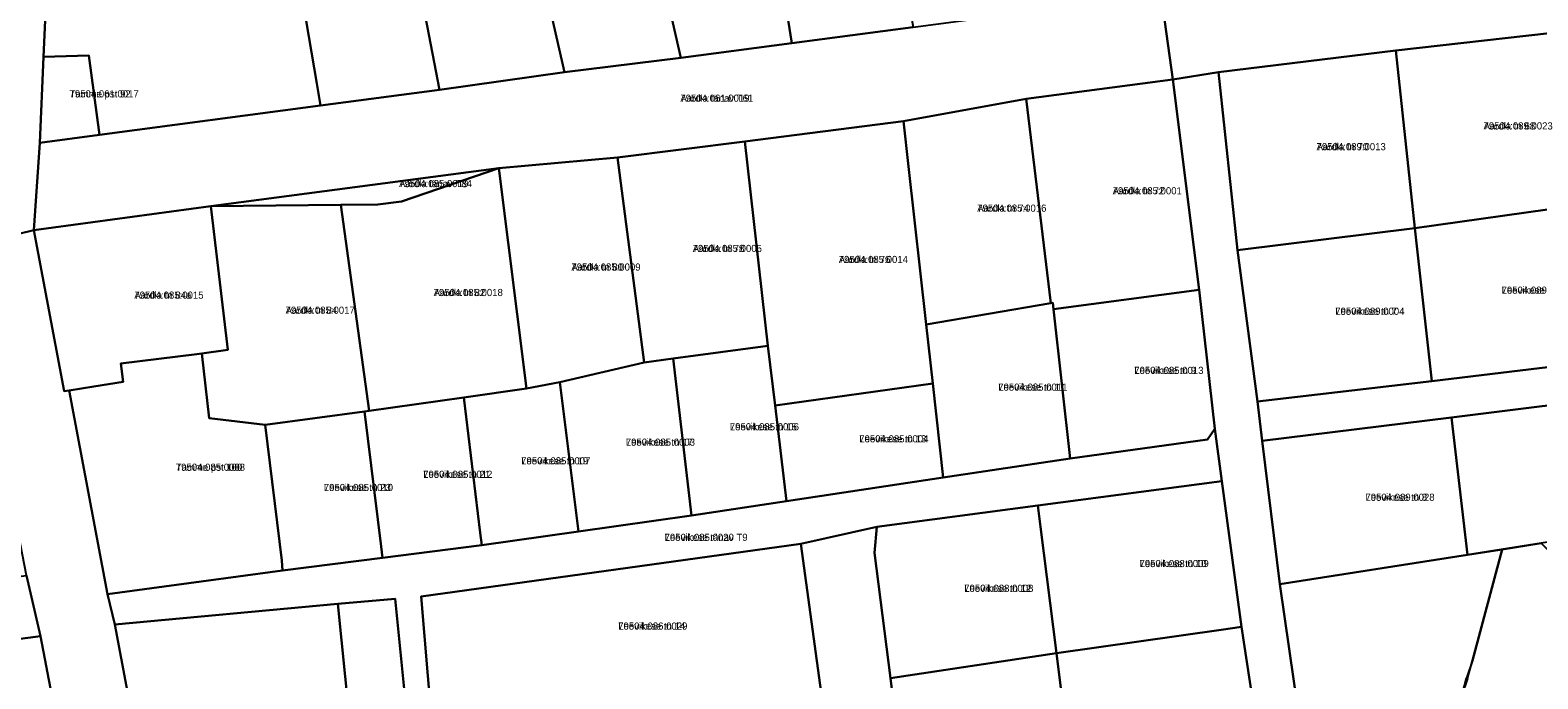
# Model space of a CAD drawing. Extents: x 643847 to 663718, y 6468443 to 6482775.
# Drawn here: x 657831.9 to 658147.9, y 6471252.2 to 6471388.2 of the extents above; entities that cross this region are included whole.
import ezdxf

# ---------------------------------------------------------------- set-up
doc = ezdxf.new("R2010")
doc.units = 0
for name, color, linetype in [('L_AADRESS', 7, 'Continuous'), ('PIIR', 7, 'Continuous'), ('TUNNUS', 7, 'Continuous')]:
    doc.layers.add(name, color=color, linetype=linetype)

msp = doc.modelspace()

# ---------------------------------------------------------------- linework, layer by layer
at = {"layer": 'PIIR'}
for points in [[(657847.52, 6471587.53), (657845.97, 6471567.52), (657842.41, 6471521.91), (657839.77, 6471486.67), (657837.5, 6471452.36), (657837.22, 6471437.59), (657835.93, 6471408.73), (657834.76, 6471382.58), (657833.95, 6471364.57), (657832.75, 6471346.26), (657818.06, 6471342.66), (657815.82, 6471355.91), (657818.38, 6471384.03), (657820.03, 6471406.57), (657821.19, 6471434.16), (657823.07, 6471447.88), (657824.85, 6471478.3), (657827.44, 6471517.38), (657828.11, 6471527.43), (657829.93, 6471552.31), (657832.8, 6471591.95)], [(658150.36, 6471387.58), (658118.18, 6471383.93), (658080.99, 6471379.35), (658071.44, 6471377.84), (658068.39, 6471400.1), (658079.89, 6471397.11), (658105.48, 6471400.5), (658104.9, 6471404.89), (658134.3, 6471408.73), (658134.78, 6471404.38), (658153.89, 6471406.9)], [(658157.59, 6471138.6), (658131.21, 6471165.2), (658120.98, 6471175.55), (658094.63, 6471202.06), (658093.37, 6471210.77), (658089.82, 6471236.97), (658085.82, 6471263.08), (658081.73, 6471293.65), (658080.28, 6471304.56), (658076.97, 6471333.75), (658071.44, 6471377.84), (658080.99, 6471379.35), (658084.98, 6471342.07), (658089.2, 6471310.31), (658090.2, 6471302.05), (658093.85, 6471272.01), (658099.83, 6471230.86), (658103.42, 6471206.17), (658120.45, 6471189), (658129.95, 6471179.44), (658131.89, 6471181.22), (658134.07, 6471179.04), (658132.12, 6471177.25), (658168.44, 6471140.66)], [(657841.55, 6471222.32), (657834.14, 6471261.11), (657831.15, 6471273.87), (657825.18, 6471304.55), (657818.06, 6471342.66), (657832.75, 6471346.26), (657839.08, 6471312.46), (657840.14, 6471312.63), (657848.14, 6471269.95), (657849.67, 6471263.57), (657853.69, 6471242.4)], [(657912.92, 6471224.23), (657908.42, 6471268.94), (657896.47, 6471267.87), (657849.67, 6471263.57), (657848.14, 6471269.95), (657884.82, 6471274.9), (657905.78, 6471277.58), (657926.6, 6471280.2), (657946.86, 6471283.07), (657970.57, 6471286.44), (657990.44, 6471289.43), (658023.3, 6471294.37), (658049.96, 6471298.38), (658078.69, 6471302.37), (658080.28, 6471304.56), (658081.73, 6471293.65), (658043.18, 6471288.51), (658009.43, 6471284.02), (657993.46, 6471280.49), (657913.9, 6471269.47), (657916.02, 6471244.49)], [(657997.92, 6471247.76), (657993.46, 6471280.49), (658009.43, 6471284.02), (658008.95, 6471278.59), (658012.26, 6471252.31), (658015.5, 6471226.51)]]:
    msp.add_lwpolyline(points, dxfattribs=at)
for points in [[(657991.61, 6471385.43), (657985.6, 6471423.21), (658002.42, 6471425.45), (658010.18, 6471426.44), (658017.04, 6471388.8)], [(657991.61, 6471385.43), (657968.36, 6471382.36), (657959.71, 6471420.04), (657980.6, 6471422.61), (657985.6, 6471423.21)], [(657943.94, 6471379.4), (657935.41, 6471416.76), (657959.71, 6471420.04), (657968.36, 6471382.36)], [(657917.76, 6471375.66), (657911.1, 6471410.21), (657935.41, 6471416.76), (657943.94, 6471379.4)], [(657846.48, 6471366.23), (657844.25, 6471382.89), (657834.76, 6471382.58), (657835.93, 6471408.73), (657840.14, 6471408.44), (657863.78, 6471413.17), (657885.43, 6471416.08), (657887.02, 6471406.64), (657892.03, 6471377.02), (657892.82, 6471372.36)], [(657892.82, 6471372.36), (657892.03, 6471377.02), (657887.02, 6471406.64), (657909.7, 6471410), (657911.1, 6471410.21), (657917.76, 6471375.66)], [(658040.27, 6471396.4), (658068.39, 6471400.1), (658071.44, 6471377.84), (658040.7, 6471373.77), (658015, 6471369.11), (657981.76, 6471364.87), (657955.06, 6471361.46), (657930.15, 6471359.24), (657869.84, 6471351.31), (657832.75, 6471346.26), (657833.95, 6471364.57), (657846.48, 6471366.23), (657892.82, 6471372.36), (657917.76, 6471375.66), (657943.94, 6471379.4), (657968.36, 6471382.36), (657991.61, 6471385.43), (658017.04, 6471388.8), (658040.78, 6471391.94)], [(658150.36, 6471387.58), (658151.63, 6471378.13), (658154.96, 6471353.35), (658154.93, 6471351.27), (658122.17, 6471346.69), (658118.18, 6471383.93)], [(657834.76, 6471382.58), (657844.25, 6471382.89), (657846.48, 6471366.23), (657833.95, 6471364.57)], [(658118.18, 6471383.93), (658122.17, 6471346.69), (658084.98, 6471342.07), (658080.99, 6471379.35)], [(658071.44, 6471377.84), (658076.97, 6471333.75), (658046.46, 6471329.72), (658046.31, 6471331.02), (658045.9, 6471330.96), (658040.7, 6471373.77)], [(658015, 6471369.11), (658040.7, 6471373.77), (658045.9, 6471330.96), (658019.74, 6471326.49), (658016.05, 6471359.62)], [(658015, 6471369.11), (658016.05, 6471359.62), (658019.74, 6471326.49), (658021.11, 6471314.07), (657988.07, 6471309.49), (657986.58, 6471321.98), (657981.76, 6471364.87)], [(657981.76, 6471364.87), (657986.58, 6471321.98), (657966.74, 6471319.33), (657960.63, 6471318.52), (657955.06, 6471361.46)], [(657955.06, 6471361.46), (657960.63, 6471318.52), (657943, 6471314.38), (657935.99, 6471313.08), (657930.15, 6471359.24)], [(657869.84, 6471351.31), (657930.15, 6471359.24), (657909.78, 6471352.28), (657904.81, 6471351.63), (657897.04, 6471351.56)], [(657897.04, 6471351.56), (657904.81, 6471351.63), (657909.78, 6471352.28), (657930.15, 6471359.24), (657935.99, 6471313.08), (657922.85, 6471311.17), (657903.02, 6471308.39)], [(657869.84, 6471351.31), (657873.39, 6471321.19), (657867.95, 6471320.36), (657866.86, 6471320.23), (657850.97, 6471318.3), (657851.42, 6471314.42), (657845.32, 6471313.44), (657840.14, 6471312.63), (657839.08, 6471312.46), (657832.75, 6471346.26)], [(657869.84, 6471351.31), (657897.04, 6471351.56), (657903.02, 6471308.39), (657902.03, 6471308.25), (657881.23, 6471305.4), (657869.44, 6471306.85), (657867.95, 6471320.36), (657873.39, 6471321.19)], [(658125.75, 6471314.57), (658122.17, 6471346.69), (658154.93, 6471351.27), (658155.26, 6471348.34), (658158.1, 6471323.5), (658158.67, 6471318.54)], [(658089.2, 6471310.31), (658084.98, 6471342.07), (658122.17, 6471346.69), (658125.75, 6471314.57)], [(658023.3, 6471294.37), (658021.11, 6471314.07), (658019.74, 6471326.49), (658045.9, 6471330.96), (658046.31, 6471331.02), (658046.46, 6471329.72), (658049.96, 6471298.38)], [(658049.96, 6471298.38), (658046.46, 6471329.72), (658076.97, 6471333.75), (658080.28, 6471304.56), (658078.69, 6471302.37)], [(658235.52, 6471328.12), (658254.35, 6471330.51), (658258.67, 6471322.85), (658224.42, 6471318.66), (658209.08, 6471316.86), (658168.46, 6471311.8), (658129.85, 6471306.99), (658090.2, 6471302.05), (658089.2, 6471310.31), (658125.75, 6471314.57), (658158.67, 6471318.54), (658182.54, 6471321.49), (658206.34, 6471324.52), (658210.61, 6471325.05)], [(657970.57, 6471286.44), (657966.74, 6471319.33), (657986.58, 6471321.98), (657988.07, 6471309.49), (657990.44, 6471289.43)], [(657840.14, 6471312.63), (657845.32, 6471313.44), (657851.42, 6471314.42), (657850.97, 6471318.3), (657866.86, 6471320.23), (657867.95, 6471320.36), (657869.44, 6471306.85), (657881.23, 6471305.4), (657884.69, 6471277.01), (657884.82, 6471274.9), (657848.14, 6471269.95)], [(657946.86, 6471283.07), (657943, 6471314.38), (657960.63, 6471318.52), (657966.74, 6471319.33), (657970.57, 6471286.44)], [(657926.6, 6471280.2), (657926.29, 6471282.77), (657922.85, 6471311.17), (657935.99, 6471313.08), (657943, 6471314.38), (657946.86, 6471283.07)], [(657990.44, 6471289.43), (657988.07, 6471309.49), (658021.11, 6471314.07), (658023.3, 6471294.37)], [(657905.78, 6471277.58), (657905.49, 6471279.89), (657902.03, 6471308.25), (657903.02, 6471308.39), (657922.85, 6471311.17), (657926.29, 6471282.77), (657926.6, 6471280.2)], [(658168.46, 6471311.8), (658171.69, 6471284.32), (658164.42, 6471283.15), (658148.64, 6471280.59), (658133.22, 6471278.18), (658129.85, 6471306.99)], [(657884.82, 6471274.9), (657884.69, 6471277.01), (657881.23, 6471305.4), (657902.03, 6471308.25), (657905.49, 6471279.89), (657905.78, 6471277.58)], [(658129.85, 6471306.99), (658133.22, 6471278.18), (658093.85, 6471272.01), (658090.2, 6471302.05)], [(658081.73, 6471293.65), (658085.82, 6471263.08), (658081.56, 6471262.47), (658047.07, 6471257.55), (658043.74, 6471284.04), (658043.18, 6471288.51)], [(658043.18, 6471288.51), (658043.74, 6471284.04), (658047.07, 6471257.55), (658012.26, 6471252.31), (658008.95, 6471278.59), (658009.43, 6471284.02)], [(657993.46, 6471280.49), (657997.92, 6471247.76), (657916.02, 6471244.49), (657913.9, 6471269.47)], [(658129.95, 6471241.88), (658130.98, 6471245.68), (658131.22, 6471245.62), (658132.97, 6471252.32), (658133.21, 6471252.25), (658134.24, 6471256.04), (658140.49, 6471279.32), (658148.64, 6471280.59), (658158.52, 6471270.64), (658154.94, 6471257.36), (658161.03, 6471247.36), (658173.12, 6471235.4), (658164, 6471224.52), (658142.75, 6471229.62), (658140.69, 6471222.12), (658125.17, 6471224.04)], [(658093.85, 6471272.01), (658133.22, 6471278.18), (658140.49, 6471279.32), (658134.24, 6471256.04), (658132.97, 6471252.32), (658133.21, 6471252.25), (658130.98, 6471245.68), (658131.22, 6471245.62), (658129.95, 6471241.88), (658125.17, 6471224.04), (658108.79, 6471226.07), (658099.83, 6471230.86)], [(657798.4, 6471269.65), (657831.15, 6471273.87), (657834.14, 6471261.11), (657805.95, 6471257.42), (657764.18, 6471252.03), (657749.28, 6471249.95), (657725.28, 6471246.6), (657703.03, 6471243.51), (657696.04, 6471242.53), (657677.42, 6471239.94), (657654.42, 6471236.8), (657651.36, 6471233.65), (657645.48, 6471248.53), (657684.62, 6471253.91), (657701.56, 6471256.35), (657724.5, 6471259.47), (657746.09, 6471262.48), (657769.87, 6471265.77)], [(657849.67, 6471263.57), (657896.47, 6471267.87), (657900.99, 6471222.91), (657898.75, 6471222.66), (657895.39, 6471222.28), (657892.84, 6471222), (657889.41, 6471246.64), (657853.69, 6471242.4)], [(657896.47, 6471267.87), (657908.42, 6471268.94), (657912.92, 6471224.23), (657908.8, 6471223.78), (657905.46, 6471223.4), (657902.1, 6471223.03), (657900.99, 6471222.91)], [(658089.82, 6471236.97), (658085.21, 6471236.36), (658050.31, 6471231.75), (658047.07, 6471257.55), (658081.56, 6471262.47), (658085.82, 6471263.08)], [(657834.14, 6471261.11), (657841.55, 6471222.32), (657831.71, 6471220.42), (657813.84, 6471216.95), (657805.95, 6471257.42)], [(658012.26, 6471252.31), (658047.07, 6471257.55), (658050.31, 6471231.75), (658015.5, 6471226.51)]]:
    msp.add_lwpolyline(points, close=True, dxfattribs=at)

# ---------------------------------------------------------------- texts
at = {"layer": 'L_AADRESS'}
for s, p in [('Tamme pst 92', (657840.21, 6471374.08)), ('Aardla tänav T61', (657968.23, 6471373.18)), ('Aardla tn 68', (658136.57, 6471367.36)), ('Aardla tn 70', (658101.58, 6471363.01)), ('Aardla tänav T84', (657909.27, 6471355.27)), ('Aardla tn 72', (658058.84, 6471353.76)), ('Aardla tn 74', (658030.45, 6471350.12)), ('Aardla tn 78', (657970.82, 6471341.67)), ('Aardla tn 76', (658001.43, 6471339.36)), ('Aardla tn 80', (657945.39, 6471337.77)), ('Aardla tn 82', (657916.52, 6471332.43)), ('Leevikese tn 5', (658140.36, 6471332.92)), ('Aardla tn 84a', (657853.79, 6471331.88)), ('Aardla tn 84', (657885.49, 6471328.72)), ('Leevikese tn 7', (658105.49, 6471328.5)), ('Leevikese tn 9', (658063.37, 6471316.1)), ('Leevikese tn 11', (658034.85, 6471312.59)), ('Leevikese tn 15', (657978.59, 6471304.28)), ('Leevikese tn 17', (657956.79, 6471301.05)), ('Leevikese tn 13', (658005.73, 6471301.75)), ('Tamme pst 100', (657862.48, 6471295.79)), ('Leevikese tn 19', (657934.86, 6471297.14)), ('Leevikese tn 23', (657893.5, 6471291.55)), ('Leevikese tn 21', (657914.32, 6471294.31)), ('Leevikese tn 8', (658111.81, 6471289.5)), ('Leevikese tänav T9', (657964.93, 6471281.09)), ('Leevikese tn 10', (658064.47, 6471275.6)), ('Leevikese tn 12', (658027.72, 6471270.41)), ('Leevikese tn 14', (657955.2, 6471262.49))]:
    msp.add_text(s, height=1.5, dxfattribs=at).set_placement(p)
at = {"layer": 'TUNNUS'}
for s, p in [('79504:061:0017', (657840.21, 6471374.08)), ('79504:061:0019', (657968.23, 6471373.18)), ('79504:089:0023', (658136.57, 6471367.36)), ('79504:089:0013', (658101.58, 6471363.01)), ('79504:085:0019', (657909.27, 6471355.27)), ('79504:085:0001', (658058.84, 6471353.76)), ('79504:085:0016', (658030.45, 6471350.12)), ('79504:085:0005', (657970.82, 6471341.67)), ('79504:085:0014', (658001.43, 6471339.36)), ('79504:085:0009', (657945.39, 6471337.77)), ('79504:089:0014', (658140.36, 6471332.92)), ('79504:085:0015', (657853.79, 6471331.88)), ('79504:085:0018', (657916.52, 6471332.43)), ('79504:085:0017', (657885.49, 6471328.72)), ('79504:089:0004', (658105.49, 6471328.5)), ('79504:085:0013', (658063.37, 6471316.1)), ('79504:085:0011', (658034.85, 6471312.59)), ('79504:085:0006', (657978.59, 6471304.28)), ('79504:085:0003', (657956.79, 6471301.05)), ('79504:085:0004', (658005.73, 6471301.75)), ('79504:085:0008', (657862.48, 6471295.79)), ('79504:085:0007', (657934.86, 6471297.14)), ('79504:085:0010', (657893.5, 6471291.55)), ('79504:085:0012', (657914.32, 6471294.31)), ('79504:089:0028', (658111.81, 6471289.5)), ('79504:085:0020', (657964.93, 6471281.09)), ('79504:088:0009', (658064.47, 6471275.6)), ('79504:088:0008', (658027.72, 6471270.41)), ('79504:086:0029', (657955.2, 6471262.49))]:
    msp.add_text(s, height=1.5, dxfattribs=at).set_placement(p)

doc.saveas('drawing.dxf')
